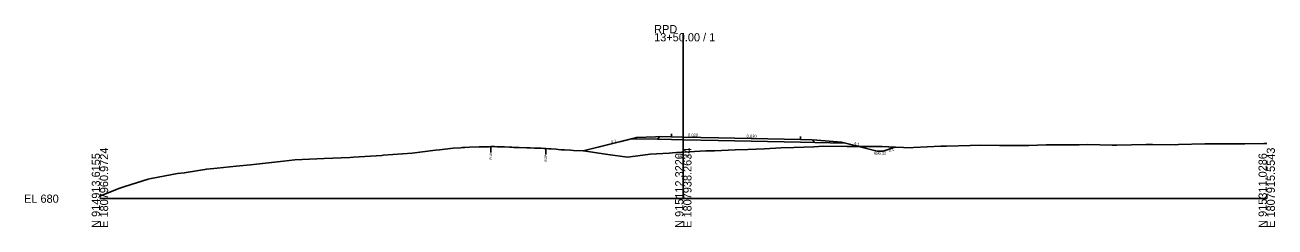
# Model space of a CAD drawing. Extents: x -26 to 403, y -10 to 8517.
# Drawn here: x -25.7 to 402.8, y 6990.3 to 7059.5 of the extents above; entities that cross this region are included whole.
import ezdxf

# ---------------------------------------------------------------- set-up
doc = ezdxf.new("R2010")
doc.units = 0
for name, color, linetype in [('Exist Cross Section Cell', 7, 'Continuous'), ('Exist XS Center Line Elevation Label', 7, 'Continuous'), ('Exist XS Ground Line', 7, 'Continuous'), ('Old_Level_10', 7, 'Continuous'), ('Prop XS Ditch Slope Text', 7, 'Continuous'), ('Prop XS Ditch Standard Text', 7, 'Continuous'), ('Prop XS Earthwork Shape', 7, 'Continuous'), ('Prop XS EOT Tick Mark', 7, 'Continuous'), ('Prop XS Finish Grade', 7, 'Continuous'), ('Prop XS Finish Grade Earthwork', 7, 'Continuous'), ('Prop XS Finish Grade Paved Shoulder', 7, 'Continuous'), ('Prop XS Finish Grade Pavement', 7, 'Continuous'), ('Prop XS Hydro Fill Slope Data', 7, 'Continuous'), ('Prop XS Pvmt Edge Slope', 7, 'Continuous'), ('Prop XS SE Text', 7, 'Continuous'), ('Prop XS Side Slope Text', 7, 'Continuous'), ('Prop XS Subgrade Earthwork', 7, 'Continuous')]:
    doc.layers.add(name, color=color, linetype=linetype)

msp = doc.modelspace()

# ---------------------------------------------------------------- linework, layer by layer
at = {"layer": 'Exist Cross Section Cell'}
for p, q in [((200, 7000), (200, 7056.66)), ((0, 7000), (200, 7000)), ((200, 7000), (400, 7000))]:
    msp.add_line(p, q, dxfattribs=at)
at = {"layer": 'Exist XS Ground Line'}
msp.add_lwpolyline([(0, 7000.84), (6.43, 7003.51), (8.56, 7004.2), (16.49, 7006.69), (17.51, 7006.87), (26.56, 7008.57), (28.88, 7008.79), (36.62, 7010.12), (40.24, 7010.46), (46.69, 7011.16), (51.61, 7011.57), (56.75, 7012.13), (62.97, 7012.84), (66.82, 7013.29), (74.33, 7013.61), (76.88, 7013.74), (85.7, 7014.14), (86.95, 7014.17), (96.63, 7014.82), (97.06, 7014.85), (107.08, 7015.6), (115.04, 7016.58), (116.43, 7016.76), (121.05, 7017.32), (123.77, 7017.45), (124.2, 7017.47), (125.09, 7017.53), (126.64, 7017.58), (130, 7017.74), (131.19, 7017.73), (131.79, 7017.76), (133.44, 7017.79), (134.05, 7017.85), (135.21, 7017.82), (136.22, 7017.79), (137.61, 7017.74), (138.74, 7017.7), (140.45, 7017.63), (141.25, 7017.6), (141.89, 7017.57), (143.77, 7017.51), (146.4, 7017.42), (147.51, 7017.39), (148.96, 7017.34), (151.31, 7017.25), (152.17, 7017.22), (152.84, 7017.19), (153.84, 7017.12), (154.65, 7017.06), (156.35, 7016.91), (157.1, 7016.83), (158.08, 7016.77), (159.22, 7016.69), (161.32, 7016.59), (162.37, 7016.52), (165.8, 7016.36), (174.14, 7015.15), (180.91, 7014.18), (186.1, 7014.84), (188.68, 7015.21), (195.12, 7015.62), (196.33, 7015.71), (197.66, 7015.81), (199.33, 7015.87), (200, 7015.91), (207.73, 7016.34), (210.7, 7016.43), (217.79, 7016.7), (222.06, 7016.83), (227.86, 7017.06), (233.43, 7017.37), (237.92, 7017.49), (244.79, 7017.71), (247.99, 7017.95), (256.15, 7017.84), (258.05, 7017.89), (267.52, 7017.88), (268.12, 7017.87), (272.78, 7017.65), (278.18, 7017.45), (278.88, 7017.47), (288.25, 7017.98), (290.25, 7018), (298.31, 7018.26), (301.61, 7018.29), (308.38, 7018.19), (312.97, 7018.18), (318.44, 7018.19), (324.34, 7018.43), (328.51, 7018.46), (335.7, 7018.48), (338.57, 7018.54), (347.06, 7018.31), (348.64, 7018.3), (358.7, 7018.54), (360.85, 7018.53), (368.77, 7018.48), (369.79, 7018.5), (378.83, 7018.75), (381.16, 7018.77), (388.9, 7018.77), (392.52, 7018.78), (398.96, 7018.87), (400, 7018.89)], dxfattribs=at)
at = {"layer": 'Old_Level_10'}
for p, q in [((134.05, 7017.85), (134.05, 7015.8)), ((152.84, 7017.19), (152.84, 7015.14))]:
    msp.add_line(p, q, dxfattribs=at)
at = {"layer": 'Prop XS Earthwork Shape'}
for points in [[(240.18, 7019.35), (245.13, 7019.25), (255.59, 7019.04), (260.19, 7017.89), (258.05, 7017.89), (256.15, 7017.84), (247.99, 7017.95), (244.79, 7017.71), (237.92, 7017.49), (233.43, 7017.37), (227.86, 7017.06), (222.06, 7016.83), (217.79, 7016.7), (210.7, 7016.43), (207.73, 7016.34), (200, 7015.91), (199.33, 7015.87), (197.66, 7015.81), (196.33, 7015.71), (195.12, 7015.62), (188.68, 7015.21), (186.1, 7014.84), (180.91, 7014.18), (174.14, 7015.15), (165.8, 7016.36), (165.7, 7016.36), (182.38, 7020.53), (191.1, 7020.35), (195.98, 7020.26), (199.98, 7020.17), (211.98, 7019.93)], [(191.1, 7020.35), (182.38, 7020.53), (165.7, 7016.36), (165.8, 7016.36), (174.14, 7015.15), (180.91, 7014.18), (186.1, 7014.84), (188.68, 7015.21), (195.12, 7015.62), (196.33, 7015.71), (197.66, 7015.81), (199.33, 7015.87), (200, 7015.91), (207.73, 7016.34), (210.7, 7016.43), (217.79, 7016.7), (222.06, 7016.83), (227.86, 7017.06), (233.43, 7017.37), (237.92, 7017.49), (244.79, 7017.71), (247.99, 7017.95), (256.15, 7017.84), (258.05, 7017.89), (260.19, 7017.89), (255.59, 7019.04), (245.13, 7019.25), (240.18, 7019.35), (211.98, 7019.93), (199.98, 7020.17), (195.98, 7020.26)], [(268.47, 7016.32), (272.51, 7017.66), (268.12, 7017.87), (267.52, 7017.88), (260.19, 7017.89), (266.47, 7016.32)]]:
    msp.add_lwpolyline(points, close=True, dxfattribs=at)
at = {"layer": 'Prop XS EOT Tick Mark'}
for p, q in [((196, 7021.17), (196, 7022.17)), ((240.19, 7020.27), (240.19, 7021.27))]:
    msp.add_line(p, q, dxfattribs=at)
at = {"layer": 'Prop XS Finish Grade'}
for p, q in [((182.38, 7020.53), (184, 7020.94)), ((190.43, 7021.19), (184, 7020.94)), ((192, 7021.25), (190.43, 7021.19)), ((244.19, 7020.19), (245.77, 7020.06)), ((245.77, 7020.06), (254.19, 7019.39)), ((255.59, 7019.04), (254.19, 7019.39))]:
    msp.add_line(p, q, dxfattribs=at)
at = {"layer": 'Prop XS Finish Grade Earthwork'}
for p, q in [((182.38, 7020.53), (165.7, 7016.36)), ((255.59, 7019.04), (266.47, 7016.32)), ((266.47, 7016.32), (268.47, 7016.32)), ((268.47, 7016.32), (272.51, 7017.66)), ((272.5, 7017.66), (272.5, 7017.66))]:
    msp.add_line(p, q, dxfattribs=at)
at = {"layer": 'Prop XS Finish Grade Paved Shoulder'}
for p, q in [((196, 7021.17), (192, 7021.25)), ((240.19, 7020.27), (244.19, 7020.19))]:
    msp.add_line(p, q, dxfattribs=at)
at = {"layer": 'Prop XS Finish Grade Pavement'}
for p, q in [((196, 7021.17), (200, 7021.09)), ((200, 7021.09), (212, 7020.85)), ((212, 7020.85), (240.19, 7020.27))]:
    msp.add_line(p, q, dxfattribs=at)
at = {"layer": 'Prop XS Hydro Fill Slope Data'}
msp.add_line((184, 7020.94), (165.7, 7016.36), dxfattribs=at)
at = {"layer": 'Prop XS Pvmt Edge Slope'}
for p, q in [((192, 7021.25), (191.1, 7020.35)), ((244.19, 7020.19), (245.13, 7019.25))]:
    msp.add_line(p, q, dxfattribs=at)
at = {"layer": 'Prop XS Subgrade Earthwork'}
for p, q in [((191.1, 7020.35), (182.38, 7020.53)), ((195.98, 7020.26), (191.1, 7020.35)), ((195.98, 7020.26), (199.98, 7020.17)), ((199.98, 7020.17), (211.98, 7019.93)), ((211.98, 7019.93), (240.18, 7019.35)), ((240.18, 7019.35), (245.13, 7019.25)), ((245.13, 7019.25), (255.59, 7019.04))]:
    msp.add_line(p, q, dxfattribs=at)

# ---------------------------------------------------------------- texts
at = {"layer": 'Exist Cross Section Cell'}
for s, p in [('RPD', (190, 7056.66)), ('13+50.00 / 1', (190, 7053.86)), ('EL 680', (-26, 6998.6))]:
    msp.add_text(s, height=2.8, dxfattribs=at).set_placement(p)
for s, p in [('N 914913.6155', (0, 6990)), ('E 1807960.9724', (2.8, 6990)), ('N 915112.3220', (200, 6990)), ('E 1807938.2634', (202.8, 6990)), ('N 915311.0286', (400, 6990)), ('E 1807915.5543', (402.8, 6990))]:
    msp.add_text(s, height=2.8, rotation=90, dxfattribs=at).set_placement(p)
at = {"layer": 'Exist XS Center Line Elevation Label'}
msp.add_text('695.91', height=1, dxfattribs=at).set_placement((198.04, 7013.91))
at = {"layer": 'Old_Level_10'}
for s, height, rotation, p in [('EOP', 0.787, 90, (134.45, 7013.4)), ('3:1', 1, 18.4349, (270.49, 7015.88)), ('EOP', 0.787, 90, (153.23, 7012.74))]:
    msp.add_text(s, height=height, rotation=rotation, dxfattribs=at).set_placement(p)
at = {"layer": 'Prop XS Ditch Slope Text'}
msp.add_text('4:1', height=1, rotation=345.9638, dxfattribs=at).set_placement((258.43, 7018.53))
at = {"layer": 'Prop XS Ditch Standard Text'}
msp.add_text('696.32', height=1, dxfattribs=at).set_placement((265.36, 7015.06))
at = {"layer": 'Prop XS SE Text'}
for p in [(201.59, 7021.32), (221.69, 7020.94)]:
    msp.add_text('0.020', height=1, rotation=358.8317, dxfattribs=at).set_placement(p)
at = {"layer": 'Prop XS Side Slope Text'}
msp.add_text('4:1', height=1, rotation=14.0362, dxfattribs=at).set_placement((175.28, 7018.91))

doc.saveas('drawing.dxf')
